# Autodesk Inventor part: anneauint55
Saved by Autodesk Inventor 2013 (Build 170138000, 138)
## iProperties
Created: 2012-12
Part Number: anneauint55
Material: Générique
Document SubType Name: Modeling
Designer: jost thierry
Density: 1 g/cm^3
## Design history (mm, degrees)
node "anneauint551"
node "anneauint55"
node "Base1"
